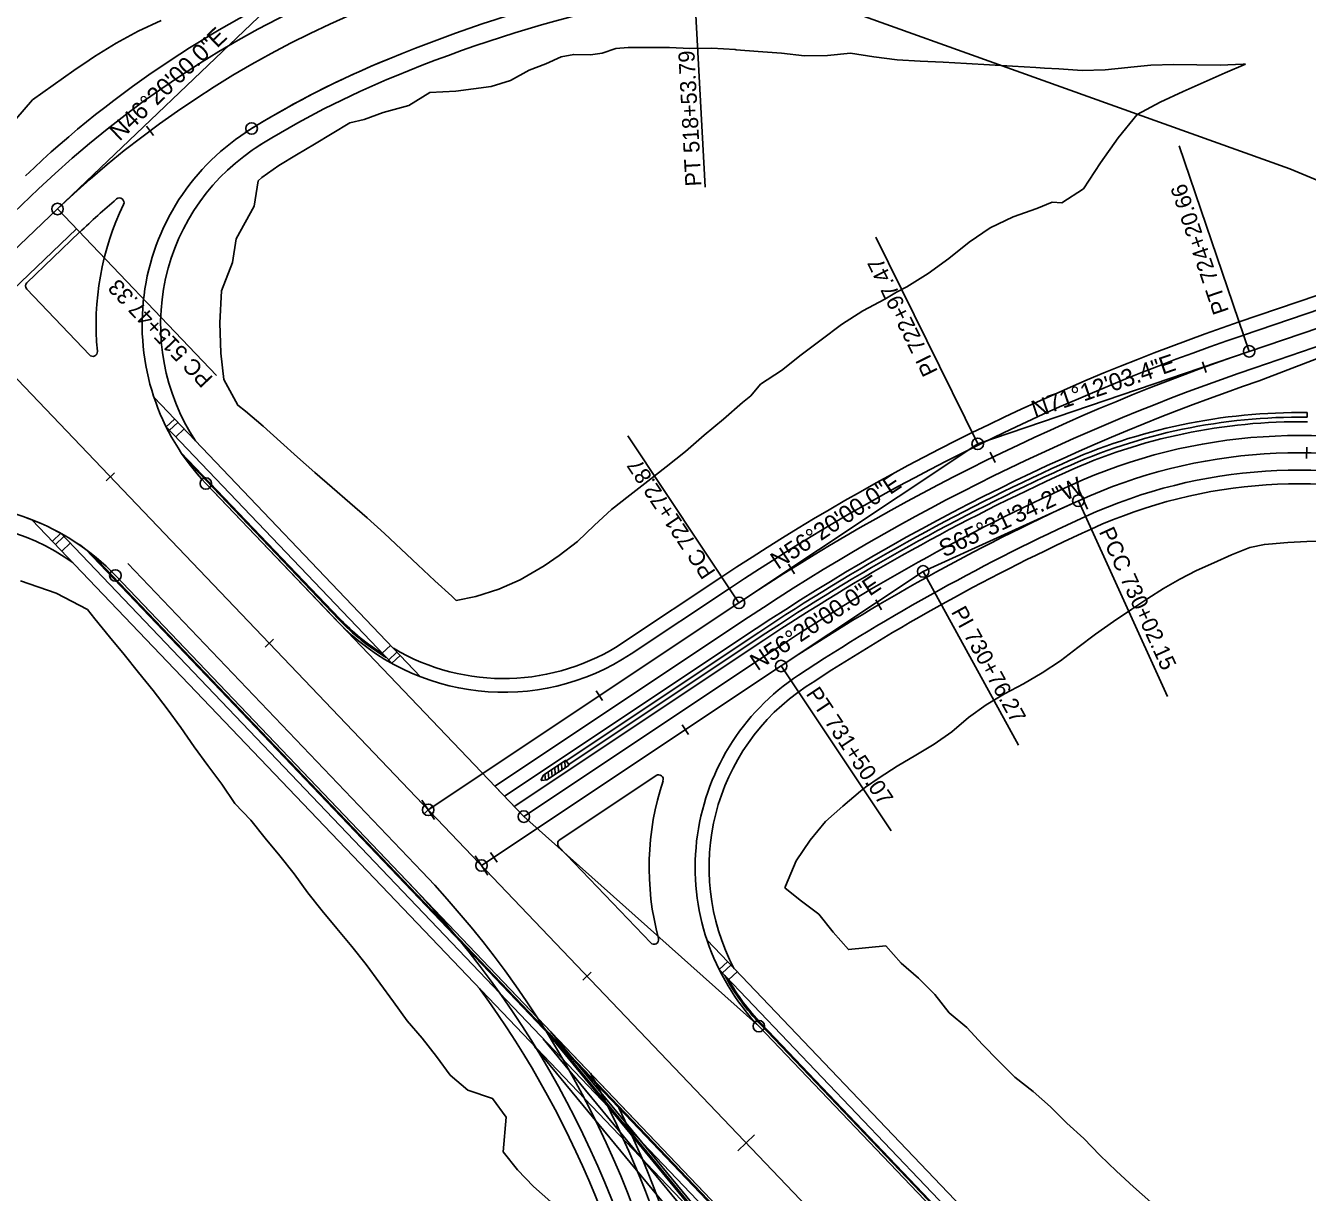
# Model space of a CAD drawing. Extents: x 1300404 to 1323571, y 234004 to 252077.
# Drawn here: x 1310184 to 1310741, y 241283 to 241789 of the extents above; entities that cross this region are included whole.
import ezdxf

# ---------------------------------------------------------------- set-up
doc = ezdxf.new("R2010")
doc.units = 0
for name, color, linetype in [('R_Attenuator', 7, 'Continuous'), ('R_Barrier Wall', 7, 'Continuous'), ('R_Const Limits', 7, 'Continuous'), ('R_Curb', 7, 'Continuous'), ('R_Draft', 7, 'Continuous'), ('R_Flooplain', 7, 'Continuous'), ('R_Future', 7, 'Continuous'), ('R_Horz Alg Annot', 7, 'Continuous'), ('R_Horz Alg Annot Leader', 7, 'Continuous'), ('R_Horz Alg Major Ticks', 7, 'Continuous'), ('R_Horz Alg Minor Ticks', 7, 'Continuous'), ('R_Horz Alg Tangents', 7, 'Continuous'), ('R_Horz Alg Tangents Text', 7, 'Continuous'), ('R_Lane Edge', 7, 'Continuous'), ('R_Proposed', 7, 'Continuous'), ('R_Shoulder', 7, 'Continuous'), ('R_Sidewalk Edge', 7, 'Continuous')]:
    doc.layers.add(name, color=color, linetype=linetype)

msp = doc.modelspace()

# ---------------------------------------------------------------- linework, layer by layer
at = {"layer": 'R_Attenuator'}
for p, q in [((1310412.72, 241463.26), (1310412.54, 241466.14)), ((1310414.16, 241464.22), (1310413.98, 241467.1)), ((1310415.6, 241465.18), (1310415.42, 241468.06)), ((1310417.05, 241466.14), (1310416.86, 241469.03)), ((1310418.49, 241467.1), (1310418.3, 241469.99)), ((1310420.1, 241468.18), (1310418.71, 241470.26)), ((1310419.93, 241468.06), (1310419.9, 241468.47)), ((1310409.02, 241463.8), (1310407.99, 241461.97)), ((1310408.33, 241461.48), (1310408.26, 241462.46)), ((1310408.32, 241461.48), (1310410.41, 241461.72)), ((1310409.82, 241461.65), (1310409.65, 241464.22)), ((1310411.28, 241462.3), (1310411.09, 241465.18))]:
    msp.add_line(p, q, dxfattribs=at)
for points in [[(1310409.02, 241463.8), (1310418.71, 241470.26)], [(1310410.41, 241461.72), (1310420.1, 241468.18)]]:
    msp.add_lwpolyline(points, dxfattribs=at)
msp.add_arc((1310408.49, 241461.95), 0.5, 176.9567, 249.5211, dxfattribs=at)
at = {"layer": 'R_Barrier Wall'}
for p, q in [((1310740.8, 241621.29), (1310740.77, 241619.29)), ((1310418.85, 241470.05), (1310502.53, 241525.79)), ((1310419.96, 241468.38), (1310503.64, 241524.12)), ((1310419.96, 241468.38), (1310418.85, 241470.05))]:
    msp.add_line(p, q, dxfattribs=at)
for centre, radius, start, end in [((1310737.29, 241372.32), 249, 89.1924, 114.4738), ((1310737.29, 241372.32), 247, 89.1924, 114.4738), ((1311023.32, 240743.92), 939.43, 114.47385, 123.66667), ((1311023.32, 240743.92), 937.43, 114.47385, 123.66667)]:
    msp.add_arc(centre, radius, start, end, dxfattribs=at)
at = {"layer": 'R_Const Limits'}
for points in [[(1310179.85, 241748.72), (1310187.06, 241757.12), (1310195.99, 241763.55), (1310204.95, 241769.88), (1310211.59, 241774.39), (1310214, 241776.06), (1310223.37, 241781.73), (1310232.94, 241787.06), (1310242.9, 241791.7)], [(1310713.95, 241772.69), (1310712.9, 241772.72), (1310702.91, 241772.17), (1310692.89, 241772.34), (1310682.87, 241772.5), (1310672.87, 241772.24), (1310664.19, 241771.34), (1310662.91, 241771.2), (1310652.95, 241770.15), (1310642.95, 241769.98), (1310632.9, 241770.57), (1310626.66, 241770.88), (1310622.85, 241771.17), (1310612.8, 241771.81), (1310602.76, 241772.39), (1310592.71, 241772.96), (1310582.67, 241773.5), (1310572.63, 241774.03), (1310562.59, 241774.57), (1310552.5, 241775.86), (1310542.4, 241777.49), (1310532.44, 241776.42), (1310522.44, 241776.25), (1310512.36, 241777.44), (1310502.3, 241778.22), (1310492.71, 241778.96), (1310492.25, 241778.99), (1310482.2, 241779.56), (1310472.62, 241779.54), (1310463.69, 241779.93), (1310454.75, 241779.92), (1310445.76, 241779.98), (1310440.44, 241779.54), (1310434.56, 241777.46), (1310429.44, 241776.71), (1310422.15, 241776.9), (1310416.67, 241775.82), (1310410.07, 241772.76), (1310402.81, 241770.07), (1310394.62, 241765.57), (1310386.34, 241762.93), (1310370.98, 241760.99), (1310359.58, 241760.38), (1310350.48, 241754.73), (1310339.31, 241751.73), (1310331.18, 241748.58), (1310324.96, 241747.19), (1310317.19, 241742.58), (1310309.49, 241737.9), (1310301.79, 241733.25), (1310294.04, 241728.7), (1310286.73, 241723.46), (1310285.06, 241721.97), (1310283.4, 241710.95), (1310275.56, 241696.75), (1310273.87, 241686.49)], [(1310371.07, 241539.73), (1310379.67, 241541.4), (1310389.57, 241544.57), (1310398.83, 241548.72), (1310407.51, 241553.71), (1310409.3, 241554.76), (1310415.87, 241559.2), (1310423.84, 241565.27), (1310431.11, 241572.41), (1310438.62, 241579.17), (1310446.46, 241585.44), (1310454.39, 241591.57), (1310462.29, 241597.75), (1310470.64, 241604.43), (1310478.88, 241611.49), (1310487.25, 241618.41), (1310495.48, 241625.62), (1310499.13, 241628.6), (1310503.28, 241633.64), (1310512.36, 241639.56), (1310520.92, 241646.43), (1310529.71, 241652.96), (1310538.52, 241659.52), (1310547.68, 241665.47), (1310557.31, 241670.56), (1310562.39, 241673.58), (1310566.78, 241675.98), (1310576.13, 241681.68), (1310585.11, 241688.21), (1310593.88, 241695.29), (1310593.96, 241695.36), (1310603.1, 241701.51), (1310612.99, 241706.29), (1310623.39, 241709.9), (1310629.93, 241712.74), (1310634.18, 241712.5), (1310643.57, 241718.54), (1310650.98, 241729.81), (1310658.72, 241740.66), (1310666.89, 241750.78), (1310676.89, 241756.13), (1310686.82, 241760.86), (1310696.01, 241764.91), (1310705.2, 241768.92), (1310713.95, 241772.69)], [(1310273.87, 241686.49), (1310269.18, 241674.17), (1310268.49, 241660.3), (1310268.85, 241647.05), (1310270.15, 241635.61), (1310276.3, 241624.5), (1310279.63, 241621.91), (1310287.24, 241615.34), (1310294.73, 241608.67), (1310302.19, 241601.97), (1310309.72, 241595.33), (1310317.28, 241588.72), (1310324.88, 241582.15), (1310332.48, 241575.58), (1310339.88, 241568.83), (1310347.18, 241561.97), (1310354.48, 241555.11), (1310361.76, 241548.24), (1310369.18, 241541.49), (1310371.07, 241539.73)], [(1310749.04, 241565.61), (1310740.68, 241565.33), (1310732.34, 241564.89), (1310724.02, 241564.21), (1310722.19, 241564.03), (1310715.82, 241562.65), (1310707.94, 241559.54), (1310700.28, 241556.09), (1310692.75, 241552.7), (1310685.45, 241548.96), (1310678.42, 241544.83), (1310671.6, 241540.5), (1310664.55, 241535.88), (1310656.58, 241530.6), (1310648.79, 241525.04), (1310641.19, 241519.19), (1310633.6, 241513.39), (1310625.69, 241508.26), (1310617.59, 241503.52), (1310609.3, 241499.14), (1310601.25, 241494.32), (1310593.6, 241488.84), (1310586.42, 241482.62), (1310578.74, 241477.27), (1310570.71, 241472.49), (1310562.69, 241467.68), (1310554.82, 241462.63), (1310548.88, 241458.65), (1310546.71, 241456.87), (1310539.06, 241450.31), (1310531.47, 241443.67), (1310524.82, 241435.62), (1310518.85, 241426.54), (1310514.16, 241415.54), (1310513.92, 241414.84)], [(1310412.25, 241278.47), (1310404.66, 241285.05), (1310397.74, 241292.27), (1310391.55, 241300.19), (1310392.84, 241315.24), (1310386.9, 241323.4), (1310376.08, 241326.89), (1310368.52, 241333.5), (1310362.56, 241341.64), (1310356.32, 241349.5), (1310349.83, 241357.13), (1310343.87, 241365.27), (1310337.99, 241373.48), (1310331.94, 241381.53), (1310325.71, 241389.41), (1310319.31, 241397.12), (1310312.94, 241404.87), (1310306.65, 241412.69), (1310300.74, 241420.87), (1310294.46, 241428.7), (1310288.14, 241436.49), (1310281.82, 241444.28), (1310274.89, 241451.5), (1310269.22, 241459.9), (1310263.24, 241468.02), (1310257.25, 241476.13), (1310251.47, 241484.43), (1310245.49, 241492.55), (1310239.39, 241500.55), (1310233.1, 241508.38), (1310226.79, 241516.17), (1310220.44, 241523.94), (1310214.15, 241531.76), (1310210.9, 241535.73), (1310197.32, 241542.9), (1310181.81, 241548.26)], [(1310513.92, 241414.84), (1310520.57, 241409.52), (1310528.62, 241403.37), (1310534.9, 241395.54), (1310541.5, 241388.02), (1310557.7, 241389.66), (1310564.32, 241382.15), (1310571.9, 241375.56), (1310578.95, 241368.47), (1310585.18, 241360.59), (1310592.91, 241354.15), (1310599.69, 241346.79), (1310606.7, 241339.66), (1310613.76, 241332.58), (1310621.79, 241326.42), (1310629.24, 241319.7), (1310636.31, 241312.62), (1310643.79, 241305.93), (1310650.76, 241298.76), (1310657.86, 241291.73), (1310665.31, 241285), (1310672.81, 241278.34)]]:
    msp.add_lwpolyline(points, dxfattribs=at)
at = {"layer": 'R_Curb'}
for p, q in [((1310251.51, 241604.02), (1310320.48, 241531.76)), ((1310253.32, 241601.4), (1310320.11, 241531.42)), ((1310210.05, 241562), (1310373.35, 241390.92)), ((1310212.58, 241560.07), (1310372.48, 241392.56)), ((1310372.48, 241392.56), (1310671.99, 241078.77)), ((1310373.35, 241390.92), (1310671.61, 241078.44)), ((1310503.29, 241355.44), (1310622.23, 241230.84)), ((1310503.65, 241355.78), (1310622.61, 241231.16))]:
    msp.add_line(p, q, dxfattribs=at)
for centre, radius, start, end in [((1310391.73, 241599.77), 99, 223.6667, 238.9473), ((1310391.73, 241599.77), 98.5, 223.6667, 237.8438), ((1310574.91, 241423.8), 99, 208.386, 223.6667), ((1310574.91, 241423.8), 98.5, 209.4895, 223.6667)]:
    msp.add_arc(centre, radius, start, end, dxfattribs=at)
at = {"layer": 'R_Draft'}
msp.add_line((1310119.62, 241618.48), (1310206.15, 241701.08), dxfattribs=at)
for centre, radius, start, end in [((1310574.96, 241212.44), 608.93, 93.92671, 112.49959), ((1310496.44, 241396.96), 408.42, 112.2282, 121.6346), ((1310334.67, 241659.55), 100, 121.6346, 223.6667), ((1310150.71, 241481.51), 100, 43.6667, 147.1004)]:
    msp.add_arc(centre, radius, start, end, dxfattribs=at)
at = {"layer": 'R_Flooplain'}
msp.add_lwpolyline([(1308850.44, 242983.42), (1308921.9, 242863.68), (1309009.78, 242685.04), (1309044.07, 242596.21), (1309055.9, 242542.38), (1309352.07, 242367.77), (1309503.16, 242292.41), (1309669.46, 242230.8), (1309815.49, 242150.85), (1309936.66, 242057.64), (1310419.39, 241839.75), (1310733.16, 241727.16), (1311043.67, 241597.79), (1311103.17, 241577.86), (1311152.77, 241553.58), (1311178, 241525.7), (1311328.48, 241486.66), (1311553.07, 241380.98), (1311870.34, 241289.99), (1312137.52, 241213.62), (1312460.11, 241035.25)], dxfattribs=at)
at = {"layer": 'R_Future'}
for p, q in [((1310228.47, 241555.74), (1310356.22, 241421.9)), ((1310504.53, 241233.21), (1310408.91, 241349.31)), ((1310506.77, 241235.21), (1310411.16, 241351.31)), ((1310411.52, 241351.65), (1310507.13, 241235.55)), ((1310412.25, 241352.34), (1310507.86, 241236.24)), ((1310500.78, 241229.89), (1310405.17, 241345.99))]:
    msp.add_line(p, q, dxfattribs=at)
for radius, end in [(432.42, 43.6667), (424.92, 43.6667), (418.92, 36.2551), (439.92, 28.6616), (443.92, 26.1864)]:
    msp.add_arc((1310043.42, 241123.33), radius, 336.8233, end, dxfattribs=at)
at = {"layer": 'R_Horz Alg Annot Leader'}
for points in [[(1310473.35, 241828.76), (1310479.21, 241719.2)], [(1310685.18, 241737.26), (1310715.59, 241647.91)], [(1310197.87, 241709.76), (1310266.91, 241637.42)], [(1310597.64, 241607.76), (1310553.44, 241697.46)], [(1310445.66, 241611.18), (1310493.94, 241538.69)], [(1310641.38, 241583.02), (1310680.08, 241498.01)], [(1310573.92, 241552.31), (1310615.3, 241476.78)], [(1310512.23, 241511.22), (1310559.98, 241439.54)]]:
    msp.add_lwpolyline(points, dxfattribs=at)
at = {"layer": 'R_Horz Alg Major Ticks'}
for points in [[(1310645.37, 241579.33), (1310641.31, 241588.47)], [(1310356.15, 241452.92), (1310361.7, 241444.6)], [(1310356.15, 241452.92), (1310361.7, 241444.6)], [(1310384.83, 241420.36), (1310379.29, 241428.68)], [(1310500.63, 241307.54), (1310493.4, 241300.63)]]:
    msp.add_lwpolyline(points, dxfattribs=at)
at = {"layer": 'R_Horz Alg Minor Ticks'}
for points in [[(1310236.6, 241745.72), (1310239.58, 241741.71)], [(1310695.24, 241643.39), (1310696.95, 241638.69)], [(1310740.51, 241601.3), (1310740.58, 241606.3)], [(1310603.02, 241604.17), (1310605.21, 241599.68)], [(1310222.64, 241595.16), (1310219.02, 241591.71)], [(1310515.4, 241555.52), (1310518.05, 241551.28)], [(1310555.91, 241535.68), (1310553.37, 241539.99)], [(1310291.69, 241522.82), (1310288.07, 241519.37)], [(1310431.9, 241500.37), (1310434.67, 241496.21)], [(1310472.06, 241481.46), (1310469.29, 241485.62)], [(1310360.73, 241450.48), (1310357.11, 241447.03)], [(1310388.83, 241426.03), (1310386.06, 241430.19)], [(1310429.78, 241378.15), (1310426.16, 241374.69)]]:
    msp.add_lwpolyline(points, dxfattribs=at)
at = {"layer": 'R_Horz Alg Tangents'}
for p, q in [((1310197.87, 241709.76), (1310313.6, 241820.22)), ((1310597.64, 241607.76), (1310715.59, 241647.91)), ((1310493.94, 241538.69), (1310597.64, 241607.76)), ((1310641.38, 241583.02), (1310573.92, 241552.31)), ((1310573.92, 241552.31), (1310512.23, 241511.22))]:
    msp.add_line(p, q, dxfattribs=at)
at = {"layer": 'R_Lane Edge'}
for p, q in [((1310713.17, 241655.01), (1311678.48, 241983.61)), ((1310718.01, 241640.81), (1311683.31, 241969.41)), ((1310165.2, 241695.16), (1310189.58, 241718.44)), ((1310184.6, 241677.73), (1310207.53, 241699.63)), ((1310184.53, 241674.91), (1310211.8, 241646.34)), ((1310262.33, 241590.5), (1310265.86, 241586.81)), ((1310265.86, 241586.81), (1310319.39, 241530.73)), ((1310223.05, 241550.56), (1310370.67, 241395.9)), ((1310447.16, 241516.54), (1310489.78, 241544.93)), ((1310387.84, 241459.01), (1310498.1, 241532.45)), ((1310400.46, 241445.79), (1310508.08, 241517.47)), ((1310416.06, 241435.75), (1310457.92, 241463.64)), ((1310400.46, 241445.79), (1310387.84, 241459.01)), ((1310415.72, 241432.7), (1310455.59, 241390.93)), ((1310370.67, 241395.9), (1310412.25, 241352.34)), ((1310502.57, 241354.75), (1310620.08, 241231.63)), ((1310412.25, 241352.34), (1311200.16, 240526.88))]:
    msp.add_line(p, q, dxfattribs=at)
for centre, radius, start, end in [((1310496.44, 241396.96), 444.42, 93.0604, 133.6667), ((1310574.96, 241212.44), 608.93, 93.92671, 112.49959), ((1310496.44, 241396.96), 408.42, 112.2282, 122.0916), ((1310334.67, 241659.55), 100, 121.6346, 223.6667), ((1310496.44, 241396.96), 418.42, 130.7161, 133.6667), ((1310334.67, 241659.55), 120, 154.2341, 185.5621), ((1310224.8, 241712.58), 2, 334.2336, 130.7163), ((1310185.98, 241676.29), 2, 133.6667, 223.6667), ((1311023.32, 240743.92), 962.43, 108.79905, 123.66667), ((1310213.25, 241647.72), 2, 223.6667, 5.562), ((1311023.32, 240743.92), 947.43, 108.79905, 123.66667), ((1310737.29, 241372.32), 239, 311.1667, 114.4738), ((1310737.29, 241372.32), 224, 311.1667, 114.4738), ((1311023.32, 240743.92), 929.43, 114.47385, 123.66667), ((1310150.71, 241481.51), 100, 43.6667, 147.1828), ((1311023.32, 240743.92), 914.43, 114.47385, 123.40686), ((1310391.73, 241599.77), 100, 223.6667, 303.6667), ((1310574.91, 241423.8), 100, 123.4069, 223.6667), ((1310574.91, 241423.8), 120, 161.7649, 194.9551), ((1310459.03, 241461.97), 2, 341.7649, 123.6667), ((1310417.17, 241434.08), 2, 123.6667, 223.6667), ((1310457.04, 241392.31), 2, 223.6667, 14.9551)]:
    msp.add_arc(centre, radius, start, end, dxfattribs=at)
at = {"layer": 'R_Proposed'}
for p, q in [((1310715.59, 241647.91), (1311680.9, 241976.51)), ((1310111.34, 241627.16), (1310197.87, 241709.76)), ((1310111.34, 241627.16), (1310197.87, 241709.76)), ((1310111.34, 241627.16), (1310197.87, 241709.76)), ((1310151.78, 241665.77), (1310197.87, 241709.76)), ((1310151.78, 241665.77), (1311952.58, 239779.15)), ((1310165.59, 241651.3), (1311952.63, 239779.09)), ((1310165.59, 241651.3), (1311952.63, 239779.09)), ((1310262.33, 241590.5), (1310400.46, 241445.79)), ((1310223.05, 241550.56), (1311374.36, 240344.37)), ((1310358.92, 241448.76), (1310493.94, 241538.69)), ((1310512.23, 241511.22), (1310382.06, 241424.52)), ((1310400.46, 241445.79), (1310502.57, 241354.75)), ((1310502.57, 241354.75), (1310620.08, 241231.63))]:
    msp.add_line(p, q, dxfattribs=at)
for centre in [(1310282.22, 241744.69), (1310197.87, 241709.76), (1310715.59, 241647.91), (1310597.64, 241607.76), (1310262.33, 241590.5), (1310641.38, 241583.02), (1310223.05, 241550.56), (1310573.92, 241552.31), (1310493.94, 241538.69), (1310512.23, 241511.22), (1310358.92, 241448.76), (1310400.46, 241445.79), (1310382.06, 241424.52), (1310502.57, 241354.75)]:
    msp.add_circle(centre, 2.5, dxfattribs=at)
for centre, radius, start, end in [((1310496.44, 241396.96), 432.42, 93.0604, 133.6667), ((1310334.67, 241659.55), 100, 121.6346, 223.6667), ((1311023.32, 240743.92), 954.93, 108.79905, 123.66667), ((1310737.29, 241372.32), 231.5, 311.1667, 114.4738), ((1311023.32, 240743.92), 921.93, 114.47385, 123.66667), ((1310150.71, 241481.51), 100, 43.6667, 147.1828)]:
    msp.add_arc(centre, radius, start, end, dxfattribs=at)
at = {"layer": 'R_Shoulder'}
for p, q in [((1310711.24, 241660.69), (1311676.55, 241989.29)), ((1310719.94, 241635.13), (1310766.63, 241653.14)), ((1310443.84, 241521.54), (1310486.46, 241549.93)), ((1310392.05, 241454.6), (1310501.42, 241527.45)), ((1310396.26, 241450.2), (1310504.75, 241522.46))]:
    msp.add_line(p, q, dxfattribs=at)
for centre, radius, start, end in [((1310496.44, 241396.96), 452.42, 93.0604, 133.6667), ((1310574.96, 241212.44), 600.93, 93.93245, 112.5014), ((1310496.44, 241396.96), 400.42, 112.2255, 122.0916), ((1310334.67, 241659.55), 92, 121.6346, 213.3062), ((1311023.32, 240743.92), 968.43, 108.79905, 123.66667), ((1311023.32, 240743.92), 941.43, 108.79905, 123.66667), ((1310737.29, 241372.32), 245, 89.1568, 114.4738), ((1311023.32, 240743.92), 935.43, 114.47385, 123.66667), ((1310737.29, 241372.32), 218, 311.1667, 114.4738), ((1310150.71, 241481.51), 92, 54.0272, 147.1828), ((1311023.32, 240743.92), 908.43, 114.47385, 123.40686), ((1310391.73, 241599.77), 94, 239.3509, 303.6667), ((1310574.91, 241423.8), 94, 123.4069, 207.9824)]:
    msp.add_arc(centre, radius, start, end, dxfattribs=at)
at = {"layer": 'R_Sidewalk Edge'}
for p, q in [((1310239.83, 241627.83), (1310355.64, 241506.51)), ((1310248.73, 241618.52), (1310245.11, 241615.06)), ((1310250.11, 241617.07), (1310246.49, 241613.62)), ((1310245.11, 241615.06), (1310343.13, 241512.38)), ((1310252.87, 241614.18), (1310249.25, 241610.72)), ((1310186.8, 241574.77), (1310385.11, 241367.02)), ((1310199.31, 241568.91), (1310195.69, 241565.45)), ((1310200.69, 241567.46), (1310197.07, 241564.01)), ((1310199.31, 241568.91), (1310378.2, 241381.49)), ((1310203.45, 241564.57), (1310199.84, 241561.11)), ((1310338.98, 241516.72), (1310342.6, 241520.17)), ((1310341.75, 241513.82), (1310345.36, 241517.28)), ((1310343.13, 241512.38), (1310346.74, 241515.83)), ((1310349.8, 241512.62), (1310355.64, 241506.51)), ((1310480.07, 241392.08), (1310628.7, 241236.37)), ((1310488.96, 241382.76), (1310485.35, 241379.31)), ((1310378.2, 241381.49), (1310655.54, 241090.93)), ((1310485.35, 241379.31), (1310624.89, 241233.12)), ((1310490.34, 241381.32), (1310486.73, 241377.86)), ((1310493.11, 241378.42), (1310489.49, 241374.97)), ((1310385.11, 241367.02), (1310651.77, 241087.64))]:
    msp.add_line(p, q, dxfattribs=at)

# ---------------------------------------------------------------- texts
at = {"layer": 'R_Horz Alg Annot'}
for s, rotation, p in [('PT 518+53.79', 93.0604, (1310477.68, 241719.76)), ('PT 724+20.66', 108.7991, (1310706.86, 241665.38)), ('PI 722+97.47', 116.2329, (1310580.47, 241639.21)), ('PC 515+47.33', 133.6667, (1310265.83, 241636.38)), ('PC 721+72.87', 123.6667, (1310484.04, 241552.09)), ('PCC 730+02.15', 294.4738, (1310650.16, 241569.58)), ('PI 730+76.27', 298.7136, (1310585.92, 241534.75)), ('PT 731+50.07', 303.6667, (1310522.79, 241499.15))]:
    msp.add_text(s, height=7, rotation=rotation, dxfattribs=at).set_placement(p)
at = {"layer": 'R_Horz Alg Tangents Text'}
for s, rotation, p in [('N46%%d20\'00.0"E', 43.6667, (1310224.83, 241738.95)), ('N71%%d12\'03.4"E', 18.7991, (1310622.51, 241618.87)), ('N56%%d20\'00.0"E', 33.6667, (1310510.84, 241552.95)), ('S65%%d31\'34.2"W', 25.0467, (1310583.03, 241558.26)), ('N56%%d20\'00.0"E', 33.6667, (1310501.94, 241508.87))]:
    msp.add_text(s, height=7.5, rotation=rotation, dxfattribs=at).set_placement(p)

doc.saveas('drawing.dxf')
